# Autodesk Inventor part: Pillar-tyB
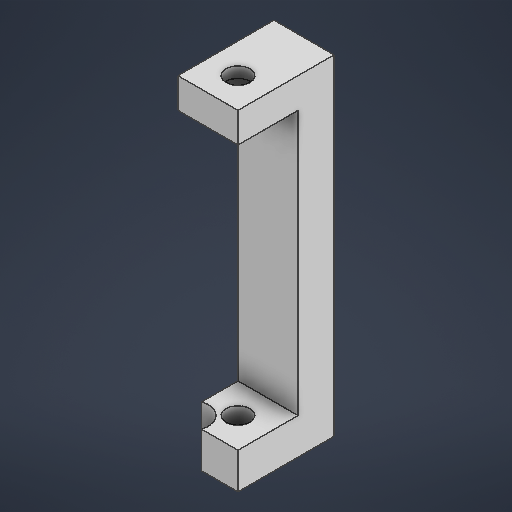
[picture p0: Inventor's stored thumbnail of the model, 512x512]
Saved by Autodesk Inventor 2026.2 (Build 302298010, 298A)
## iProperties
Created: 2026-05
Part Number: Pillar-tyB
Material: 일반
Document SubType Name: Modeling
Designer: work
Density: 1 g/cm^3
Appearance: 기본값
Author: work
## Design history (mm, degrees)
sketch "스케치1"
  geometry: L1 (-5, 5)-(5, 5); L2 (5, 5)-(5, -5); L3 (5, -5)-(-5, -5); L4 (-5, -5)-(-5, 5); L5 (-5, 5)-(5, -5); L6 (5, 5)-(-5, -5); L7 (5, -5)-(-5, -5); L8 (-5, -5)-(-5, -11); L9 (-5, -11)-(5, -11); L10 (5, -11)-(5, -5); C1 r 2 at (0, 0); C2 r 3.1 at (4, 4); 3 further points
  constraints: 20 end point, 4 parallel, 2 centre point, 2 horizontal, 2 midpoint, 2 perpendicular, 1 coincident
  dimensions: "d0" = 4 diameter of C1; "d1" = 10 distance of L2.end L3.end; "d2" = 10 distance of L1.end L2.end; "d3" = 6 distance of L9.end L2.end; "d4" = 6.2 diameter of C2; "d5" = 4 horizontal distance of point (0, 0) C2.centre; "d6" = 4 horizontal distance of C2.centre point (0, 0)
extrude "돌출1" new body sketch "스케치1" distance "d7" = 6; taper "d8" = 0 deg
extrude "돌출2" join sketch "스케치1" distance "d9" = 50; taper "d10" = 0 deg
sketch "스케치2"
  geometry: L1 (5, 5)-(-5, 5) reference; L2 (-5, 5)-(-5, -1.066) reference; L3 (-1.066, -5)-(5, -5) reference; L4 (5, -5)-(5, 5) reference; L5 (-5, 5)-(5, 5) reference; L6 (5, 5)-(5, 11) reference; L7 (5, 11)-(-5, 11) reference; L8 (-5, 11)-(-5, 5) reference; L9 (-5, -1.066)-(-5, -5); L10 (-5, -5)-(-1.066, -5); C1 r 2 at (0, 0) reference; A1 r 3.1 centre (-4, -4) between (-1.066, -5) and (-5, -1.066) reference; 3 further points
  constraints: 4 end point, 1 perpendicular, 1 vertical
extrude "돌출3" join sketch "스케치2" distance "d11" = 5; taper "d12" = 0 deg
sketch "스케치3"
  geometry: C1 r 2 at (0, 0) reference; 2 further points
  constraints: 1 coincident
hole "구멍1" sketch "스케치3" at (0, 0) diameter "d13" = 4; stored, may be unused: countersink angle "d17" = 90 deg, drill point angle "d19" = 118 deg; dims "d14" = 6, "d15" = 6.2, "d16" = 3.2, "d18" = 8
node "솔리드1"
node "투영된 루프1"
node "투영된 루프2"
feature "A9D066F2-1C7D-4E18-AEED-F7BC21143FA4" dims "d13" = 4, "d14" = 6, "d15" = 6.2, "d16" = 3.2, "d17" = 90 deg, "d18" = 8, "d19" = 118 deg
